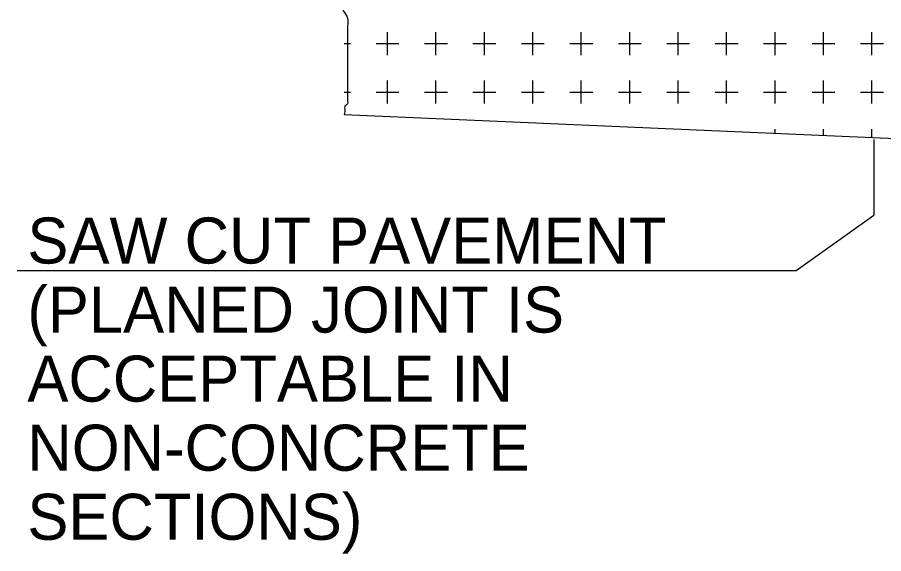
# Model space of a CAD drawing. Extents: x -28.8 to 41.7, y 0 to 25.4.
# Drawn here: x 9.98 to 12.616, y 6.101 to 7.732 of the extents above; entities that cross this region are included whole.
import ezdxf

# ---------------------------------------------------------------- set-up
doc = ezdxf.new("R2010")
doc.units = 0
doc.layers.add('Default', color=7, linetype='Continuous')

msp = doc.modelspace()

# ---------------------------------------------------------------- linework, layer by layer
at = {"layer": 'Default'}
for p, q in [((11.1064, 7.6521), (11.1064, 7.6869)), ((11.2538, 7.6174), (11.2538, 7.6869)), ((11.4013, 7.6521), (11.4013, 7.6869)), ((11.5486, 7.6174), (11.5486, 7.6869)), ((11.6961, 7.6521), (11.6961, 7.6869)), ((11.8434, 7.6174), (11.8434, 7.6869)), ((11.9909, 7.6521), (11.9909, 7.6869)), ((12.1383, 7.6174), (12.1383, 7.6869)), ((12.2858, 7.6521), (12.2858, 7.6869)), ((12.4331, 7.6174), (12.4331, 7.6869)), ((12.5804, 7.6521), (12.5804, 7.6869)), ((10.9749, 7.6521), (10.9936, 7.6521)), ((11.0716, 7.6521), (11.1064, 7.6521)), ((11.1064, 7.6174), (11.1064, 7.6521)), ((11.1064, 7.6521), (11.1411, 7.6521)), ((11.2191, 7.6521), (11.2886, 7.6521)), ((11.3664, 7.6521), (11.4013, 7.6521)), ((11.4013, 7.6174), (11.4013, 7.6521)), ((11.4013, 7.6521), (11.4359, 7.6521)), ((11.5139, 7.6521), (11.5834, 7.6521)), ((11.6613, 7.6521), (11.6961, 7.6521)), ((11.6961, 7.6174), (11.6961, 7.6521)), ((11.6961, 7.6521), (11.7308, 7.6521)), ((11.8088, 7.6521), (11.8783, 7.6521)), ((11.9561, 7.6521), (11.9909, 7.6521)), ((11.9909, 7.6174), (11.9909, 7.6521)), ((11.9909, 7.6521), (12.0256, 7.6521)), ((12.1036, 7.6521), (12.1731, 7.6521)), ((12.2509, 7.6521), (12.2858, 7.6521)), ((12.2858, 7.6174), (12.2858, 7.6521)), ((12.2858, 7.6521), (12.3204, 7.6521)), ((12.3983, 7.6521), (12.4678, 7.6521)), ((12.5458, 7.6521), (12.5804, 7.6521)), ((12.5804, 7.6174), (12.5804, 7.6521)), ((12.5804, 7.6521), (12.6153, 7.6521)), ((11.1064, 7.4699), (11.1064, 7.5394)), ((11.2538, 7.5047), (11.2538, 7.5394)), ((11.4013, 7.4699), (11.4013, 7.5394)), ((11.5486, 7.5047), (11.5486, 7.5394)), ((11.6961, 7.4699), (11.6961, 7.5394)), ((11.8434, 7.5047), (11.8434, 7.5394)), ((11.9909, 7.4699), (11.9909, 7.5394)), ((12.1383, 7.5047), (12.1383, 7.5394)), ((12.2858, 7.4699), (12.2858, 7.5394)), ((12.4331, 7.5047), (12.4331, 7.5394)), ((12.5804, 7.4699), (12.5804, 7.5394)), ((10.9749, 7.5047), (10.9936, 7.5047)), ((11.0716, 7.5047), (11.1411, 7.5047)), ((11.2191, 7.5047), (11.2538, 7.5047)), ((11.2538, 7.4699), (11.2538, 7.5047)), ((11.2538, 7.5047), (11.2886, 7.5047)), ((11.3664, 7.5047), (11.4359, 7.5047)), ((11.5139, 7.5047), (11.5486, 7.5047)), ((11.5486, 7.4699), (11.5486, 7.5047)), ((11.5486, 7.5047), (11.5834, 7.5047)), ((11.6613, 7.5047), (11.7308, 7.5047)), ((11.8088, 7.5047), (11.8434, 7.5047)), ((11.8434, 7.4699), (11.8434, 7.5047)), ((11.8434, 7.5047), (11.8783, 7.5047)), ((11.9561, 7.5047), (12.0256, 7.5047)), ((12.1036, 7.5047), (12.1383, 7.5047)), ((12.1383, 7.4699), (12.1383, 7.5047)), ((12.1383, 7.5047), (12.1731, 7.5047)), ((12.2509, 7.5047), (12.3204, 7.5047)), ((12.3983, 7.5047), (12.4331, 7.5047)), ((12.4331, 7.4699), (12.4331, 7.5047)), ((12.4331, 7.5047), (12.4678, 7.5047)), ((12.5458, 7.5047), (12.6153, 7.5047)), ((12.2858, 7.3796), (12.2858, 7.3921)), ((12.4331, 7.3732), (12.4331, 7.3921)), ((12.5804, 7.3669), (12.5804, 7.3921)), ((12.5867, 7.3603), (12.5867, 7.13)), ((12.35, 6.9625), (12.5867, 7.13)), ((9.9799, 6.9625), (12.35, 6.9625))]:
    msp.add_line(p, q, dxfattribs=at)
msp.add_lwpolyline([(10.9749, 7.4364), (13.3289, 7.3344), (13.3474, 7.3321)], dxfattribs=at)
msp.add_spline([(10.9749, 8.6509), (10.9696, 8.6349), (10.9804, 8.6229), (10.9804, 8.6107), (10.9804, 8.6067), (10.9804, 8.5946), (10.9804, 8.5824), (10.9739, 8.5439), (10.9739, 8.5277), (10.9804, 8.5116), (10.9804, 8.5034), (10.9804, 8.4994), (10.9804, 8.4912), (10.9804, 8.4811), (10.9804, 8.4771), (10.9749, 8.4631), (10.9891, 8.4447), (10.9891, 8.4286), (10.9891, 8.4244), (10.9826, 8.4122), (10.9826, 8.4042), (10.9826, 8.3921), (10.9826, 8.3739), (10.9826, 8.3617), (10.9826, 8.3434), (10.9761, 8.3212), (10.9761, 8.2766), (10.9761, 8.2604), (10.9761, 8.2281), (10.9761, 8.1997), (10.9761, 8.1774), (10.9761, 8.1652), (10.9761, 8.1391), (10.9761, 8.1349), (10.9761, 8.1227), (10.9761, 8.1066), (10.9761, 8.0884), (10.9761, 8.0802), (10.9761, 8.0579), (10.9761, 8.0337), (10.9761, 8.0094), (10.9804, 7.9952), (10.9804, 7.9871), (10.9804, 7.9791), (10.9804, 7.9587), (10.9804, 7.9506), (10.9804, 7.9426), (10.9739, 7.9284), (10.9676, 7.8961), (10.9676, 7.8879), (10.9676, 7.8697), (10.9676, 7.8616), (10.9676, 7.8494), (10.9676, 7.8312), (10.9676, 7.8191), (10.9676, 7.8009), (10.9676, 7.7806), (10.9676, 7.7684), (10.9718, 7.7522), (10.9848, 7.7299), (10.9848, 7.7057), (10.9848, 7.6814), (10.9848, 7.6611), (10.9848, 7.6247), (10.9848, 7.5882), (10.9848, 7.5661), (10.9848, 7.5397), (10.9848, 7.5214), (10.9848, 7.5032), (10.9848, 7.4992), (10.9848, 7.4809), (10.9848, 7.4769), (10.9848, 7.4687), (10.9761, 7.4607), (10.9761, 7.4526), (10.9749, 7.4364)], degree=3, dxfattribs=at)

# ---------------------------------------------------------------- texts
for s, p in [('SAW CUT PAVEMENT', (10.0105, 6.9833)), ('(PLANED JOINT IS', (10.0105, 6.7733)), ('ACCEPTABLE IN', (10.0105, 6.5633)), ('NON-CONCRETE', (10.0105, 6.3533)), ('SECTIONS)', (10.0105, 6.1433))]:
    msp.add_text(s, height=0.14, dxfattribs=at).set_placement(p)

doc.saveas('drawing.dxf')
